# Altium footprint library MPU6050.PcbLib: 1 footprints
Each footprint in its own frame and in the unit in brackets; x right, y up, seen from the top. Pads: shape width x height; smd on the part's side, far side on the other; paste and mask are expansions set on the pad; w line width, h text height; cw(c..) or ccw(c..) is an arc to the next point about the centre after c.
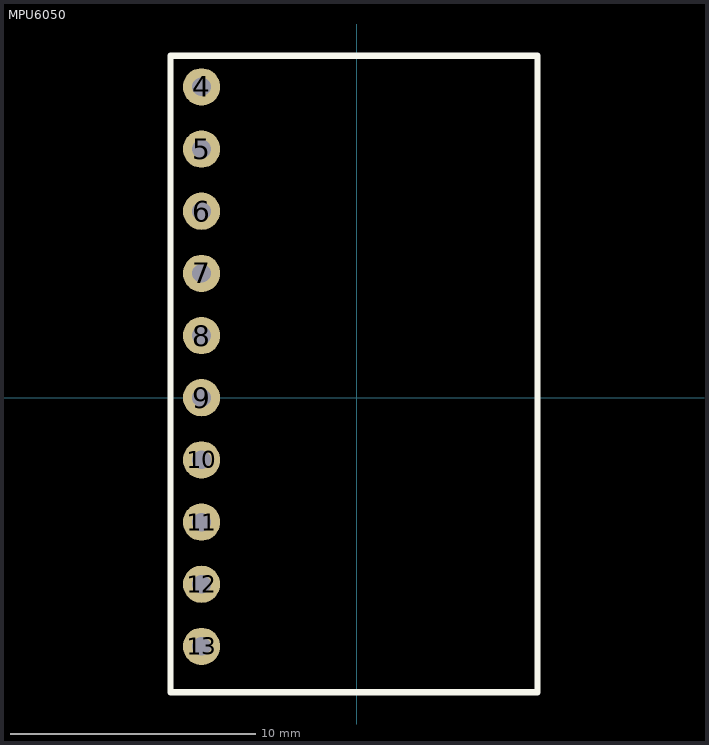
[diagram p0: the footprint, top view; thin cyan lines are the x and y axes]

## MPU6050 [mil]
pads (10):
  round 60 hole 30: 4(-250,500) 5(-250,400) 6(-250,300) 7(-250,200) 8(-250,100) 9(-250,0) 10(-250,-100) 11(-250,-200) 12(-250,-300) 13(-250,-400)
Top Overlay:
  lines w10: -300,-473.62 290.55,-473.62 290.55,550 -300,550 -300,-473.62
